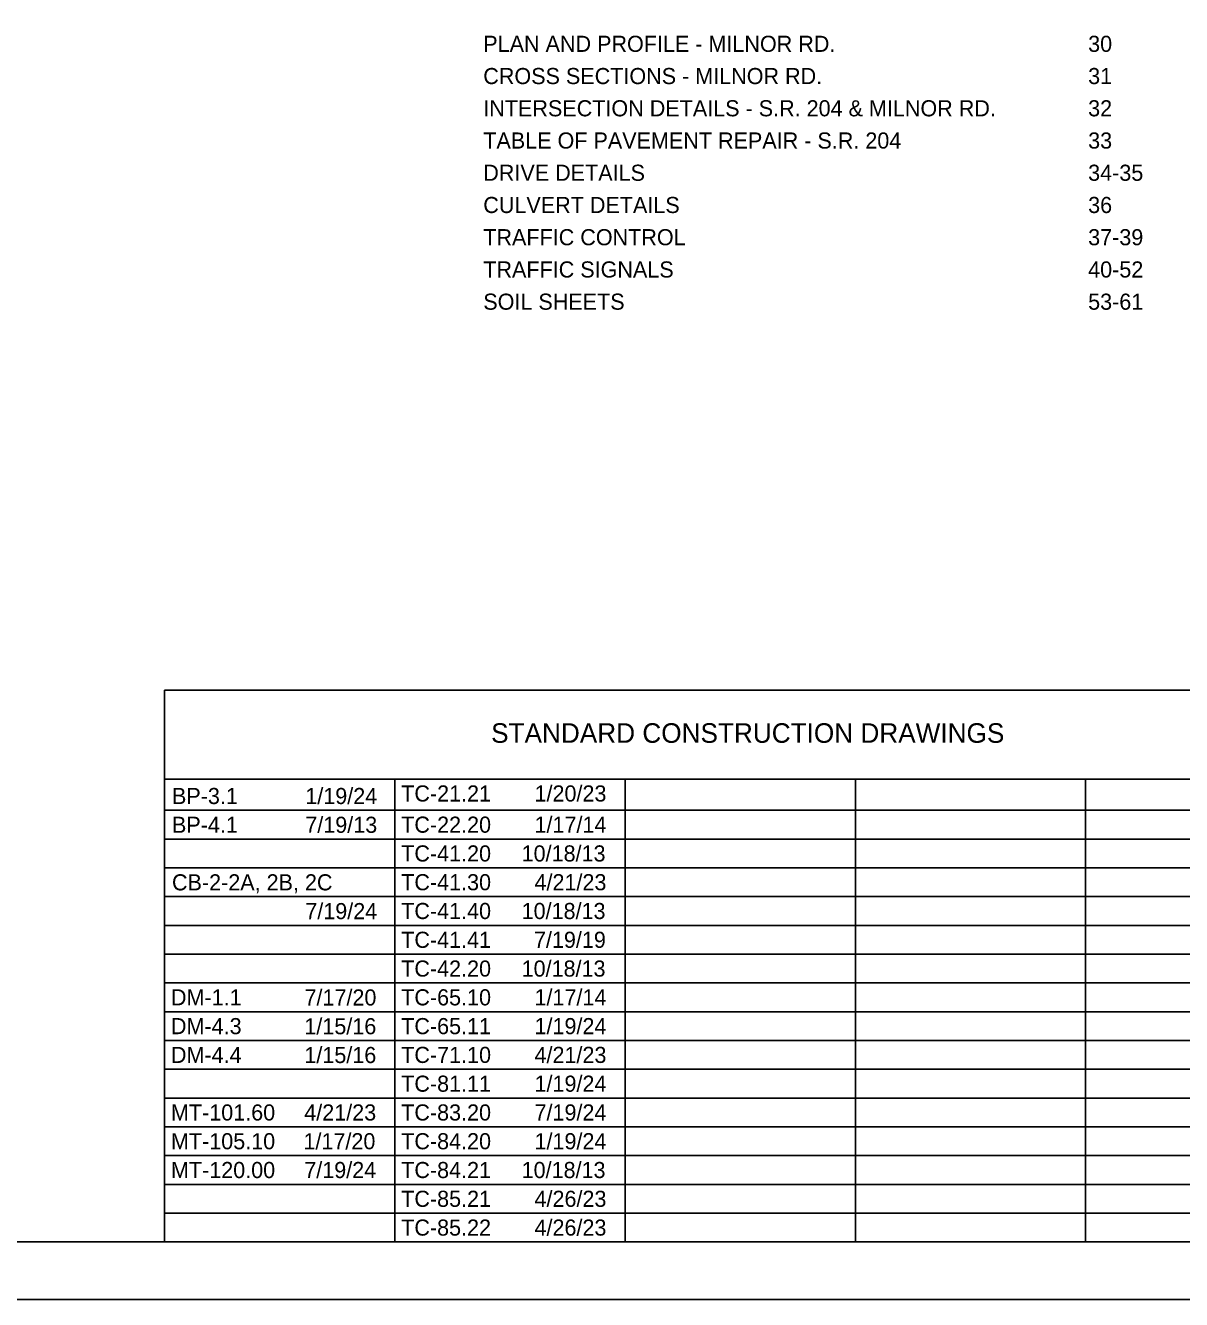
# Model space of a CAD drawing. Extents: x 0 to 34, y 0 to 22.
# Drawn here: x 10.04 to 20.08, y 0 to 11.07 of the extents above; entities that cross this region are included whole.
import ezdxf

# ---------------------------------------------------------------- set-up
doc = ezdxf.new("R2010")
doc.units = 0
for name, color, linetype in [('SH_Border', 7, 'Continuous'), ('SH_Cut_Line', 7, 'Continuous'), ('SH_Data', 7, 'Continuous'), ('SH_Text', 7, 'Continuous')]:
    doc.layers.add(name, color=color, linetype=linetype)

msp = doc.modelspace()

# ---------------------------------------------------------------- linework, layer by layer
at = {"layer": 'SH_Border'}
msp.add_lwpolyline([(1.5, 21.5), (33.5, 21.5), (33.5, 0.5), (1.5, 0.5)], close=True, dxfattribs=at)
at = {"layer": 'SH_Cut_Line'}
msp.add_lwpolyline([(0, 0), (34, 0), (34, 22), (0, 22)], close=True, dxfattribs=at)
at = {"layer": 'SH_Data'}
for p, q in [((11.25, 5.292), (24.7, 5.292)), ((11.25, 0.5), (11.25, 5.292)), ((11.25, 4.521), (24.7, 4.521)), ((13.25, 0.5), (13.25, 4.521)), ((15.25, 0.5), (15.25, 4.521)), ((17.25, 0.5), (17.25, 4.521)), ((19.25, 0.5), (19.25, 4.521)), ((11.25, 4.25), (24.7, 4.25)), ((11.25, 4), (24.7, 4)), ((11.25, 3.75), (24.7, 3.75)), ((11.25, 3.5), (24.7, 3.5)), ((11.25, 3.25), (24.7, 3.25)), ((11.25, 3), (24.7, 3)), ((11.25, 2.75), (24.7, 2.75)), ((11.25, 2.5), (24.7, 2.5)), ((11.25, 2.25), (24.7, 2.25)), ((11.25, 2), (24.7, 2)), ((11.25, 1.75), (24.7, 1.75)), ((11.25, 1.5), (24.7, 1.5)), ((11.25, 1.25), (24.7, 1.25)), ((11.25, 1), (24.7, 1)), ((11.25, 0.75), (24.7, 0.75))]:
    msp.add_line(p, q, dxfattribs=at)

# ---------------------------------------------------------------- texts
at = {"layer": 'SH_Text'}
for s, height, p in [('PLAN AND PROFILE - MILNOR RD.', 0.14, (14.018, 10.838)), ('30', 0.14, (19.272, 10.838)), ('CROSS SECTIONS - MILNOR RD.', 0.14, (14.018, 10.558)), ('31', 0.14, (19.272, 10.558)), ('INTERSECTION DETAILS - S.R. 204 & MILNOR RD.', 0.14, (14.018, 10.278)), ('32', 0.14, (19.272, 10.278)), ('TABLE OF PAVEMENT REPAIR - S.R. 204', 0.14, (14.018, 9.998)), ('33', 0.14, (19.272, 9.998)), ('DRIVE DETAILS', 0.14, (14.018, 9.718)), ('34-35', 0.14, (19.272, 9.718)), ('CULVERT DETAILS', 0.14, (14.018, 9.438)), ('36', 0.14, (19.272, 9.438)), ('TRAFFIC CONTROL', 0.14, (14.018, 9.158)), ('37-39', 0.14, (19.272, 9.158)), ('TRAFFIC SIGNALS', 0.14, (14.018, 8.878)), ('40-52', 0.14, (19.272, 8.878)), ('SOIL SHEETS', 0.14, (14.018, 8.598)), ('53-61', 0.14, (19.272, 8.598)), ('STANDARD CONSTRUCTION DRAWINGS', 0.17, (14.086, 4.836)), ('BP-3.1', 0.14, (11.314, 4.304)), ('1/19/24', 0.14, (12.472, 4.304)), ('TC-21.21', 0.14, (13.305, 4.326)), ('1/20/23', 0.14, (14.463, 4.326)), ('BP-4.1', 0.14, (11.314, 4.054)), ('7/19/13', 0.14, (12.472, 4.054)), ('TC-22.20', 0.14, (13.305, 4.055)), ('1/17/14', 0.14, (14.463, 4.055)), ('TC-41.20', 0.14, (13.305, 3.805)), ('10/18/13', 0.14, (14.351, 3.805)), ('CB-2-2A, 2B, 2C', 0.14, (11.314, 3.554)), ('TC-41.30', 0.14, (13.305, 3.555)), ('4/21/23', 0.14, (14.463, 3.555)), ('7/19/24', 0.14, (12.472, 3.304)), ('TC-41.40', 0.14, (13.305, 3.305)), ('10/18/13', 0.14, (14.351, 3.305)), ('TC-41.41', 0.14, (13.305, 3.055)), ('7/19/19', 0.14, (14.458, 3.055)), ('TC-42.20', 0.14, (13.305, 2.805)), ('10/18/13', 0.14, (14.351, 2.805)), ('DM-1.1', 0.14, (11.305, 2.555)), ('7/17/20', 0.14, (12.465, 2.554)), ('TC-65.10', 0.14, (13.305, 2.555)), ('1/17/14', 0.14, (14.463, 2.555)), ('DM-4.3', 0.14, (11.305, 2.305)), ('1/15/16', 0.14, (12.464, 2.304)), ('TC-65.11', 0.14, (13.305, 2.305)), ('1/19/24', 0.14, (14.463, 2.305)), ('DM-4.4', 0.14, (11.305, 2.055)), ('1/15/16', 0.14, (12.464, 2.054)), ('TC-71.10', 0.14, (13.305, 2.055)), ('4/21/23', 0.14, (14.463, 2.055)), ('TC-81.11', 0.14, (13.305, 1.805)), ('1/19/24', 0.14, (14.463, 1.805)), ('MT-101.60', 0.14, (11.305, 1.555)), ('4/21/23', 0.14, (12.463, 1.555)), ('TC-83.20', 0.14, (13.305, 1.555)), ('7/19/24', 0.14, (14.463, 1.555)), ('MT-105.10', 0.14, (11.305, 1.305)), ('1/17/20', 0.14, (12.456, 1.305)), ('TC-84.20', 0.14, (13.305, 1.305)), ('1/19/24', 0.14, (14.463, 1.305)), ('MT-120.00', 0.14, (11.305, 1.055)), ('7/19/24', 0.14, (12.463, 1.055)), ('TC-84.21', 0.14, (13.305, 1.055)), ('10/18/13', 0.14, (14.351, 1.055)), ('TC-85.21', 0.14, (13.305, 0.805)), ('4/26/23', 0.14, (14.463, 0.805)), ('TC-85.22', 0.14, (13.305, 0.555)), ('4/26/23', 0.14, (14.463, 0.555))]:
    msp.add_text(s, height=height, dxfattribs=at).set_placement(p)

doc.saveas('drawing.dxf')
